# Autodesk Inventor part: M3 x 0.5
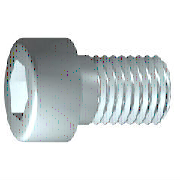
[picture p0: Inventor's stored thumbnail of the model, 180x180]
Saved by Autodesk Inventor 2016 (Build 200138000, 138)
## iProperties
IsCustomPart: 0
Created: 2015-10
Part Number: M3 x 0.5
Material: 강, 연강
Description: 6각머리 태핑 나사
Document SubType Name: Modeling
Standard: KS B 1003
Designer: mdu
Standards Organization: KS
Language: ko-KR
Size Designation: M 3 x 12
Categories: <MemberInstance><Categories><Category DisplayName="조임쇠" InternalName="e4da775c-781d-43d5-af7c-5136215cf5a6" Mnemonic="FSTN"><Category DisplayName="볼트" InternalN
Density: 1 g/cm^3
Appearance: 강철
Author: mdu
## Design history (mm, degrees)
sketch "스케치1"
  geometry: L1 (-0.867, 0)-(12, 0); L2 (12, 0)-(12, 1.5); L3 (12, 1.5)-(1.25, 1.5); L4 (1.25, 1.5)-(0.943, 1.5); L5 (0.943, 1.5)-(0, 1.5); L6 (0, 1.5)-(0, 2.75); L7 (0, 2.75)-(-3, 2.75); L8 (-3, 2.75)-(-3, 1.443); L9 (-3, 1.443)-(-1.7, 1.443); L10 (-1.7, 1.443)-(-0.867, 0); L11 (-6, 0)-(15, 0) reference; L12 (0, -0.55)-(0, 3.3) reference; L13 (1.25, 1.5)-(0, 1.5)
  constraints: 22 end point, 6 parallel, 2 collinear, 2 perpendicular, 1 horizontal, 1 point on line
  dimensions: "d1" = 10.75 distance from line of L3.end L2 (= GEL); "d2" = 0.30683 distance of L4.end L3.end (computed from GAL); "d3" = 3 distance between parallel lines of L8 L6 (= KOH); "d4" = 1.3 distance of L8.end L9.end (= INTI); "d5" = 60 deg angle of L10 L1; "d6" = 3 diameter of L3 L1 (= GD); "d7" = 3 diameter of L5 L1 (= BDM); "d8" = 2.88675 diameter of L9 L1 (= 1.1547 x SW); "d9" = 5.5 diameter of L7 L1 (= KOD); "d26" = 12 distance between parallel lines of L12 L2 (= NLG)
revolve "본체" sketch "스케치1" stored, may be unused: angle "d10" = 90 deg
sketch "스케치2"
  geometry: L1 (0, -3.85)-(0, 3.85) reference; L2 (-3.85, 0)-(3.85, 0) reference; L3 (1.443, 0)-(0.722, -1.25); L4 (0.722, -1.25)-(-0.722, -1.25); L5 (-0.722, -1.25)-(-1.443, 0); L6 (-1.443, 0)-(-0.722, 1.25); L7 (-0.722, 1.25)-(0.722, 1.25); L8 (0.722, 1.25)-(1.443, 0); 2 further points
  constraints: 12 end point, 1 coincident, 1 horizontal alignment, 1 point on line, 12 other
extrude "슬롯" join sketch "스케치2" stored distance "d11" = 10; taper "d12" = 0 deg
workplane "Work Plane1"
fillet "Fillet2" dims "d30" = 0.1 (= R)
body "Solid1"
fillet "모깎기1" dims "d17" = 0.3 (= RR)
feature "스레드" dims "d13" = 10.75 (= GEL), "d14" = 0
chamfer "모따기1" distance "d15" = 0.30673 (= -0.5 x SPD + 0.5 x GD); stored, may be unused: second distance "d16" = 0.30673 (= GUL), angle "d27" = 45 deg
other parameters: "GD" = 3 (= NND) [user parameter; used in 2 equation terms], "NLG" = 12 [user parameter; used in 1 equation term], "GEL" = 10.75 [user parameter; used in 2 equation terms], "KOD" = 5.5 [user parameter; used in 1 equation term], "KOH" = 3 [user parameter; used in 1 equation term], "INTI" = 1.3 [user parameter; used in 1 equation term], "GAL" = 0.30673 (= 0.61345 x PTC) [user parameter; used in 1 equation term], "GUL" = 0.30673 (= 0.61345 x PTC) [user parameter; used in 1 equation term], "BDM" = 3 (= NND) [user parameter; used in 1 equation term], "SW" = 2.5 [user parameter; used in 2 equation terms], "RR" = 0.3 [user parameter; used in 1 equation term], "SPD" = 2.38655 (= NND - 1.2269 x PTC) [user parameter; used in 1 equation term], "d19" = 0, "d28" = 0, "d29" = 0, "R" = 0.1 [user parameter; used in 1 equation term], "PHH" = 0.1 [user parameter], "GD1" = 2.38655 (= THREADDIA - 1.2269 x PTC) [user parameter], "THREADDIA" = 3 [user parameter; used in 1 equation term], "FAWI" = 45 deg [user parameter], "PTC" = 0.5 [user parameter; used in 5 equation terms], "NND" = 3 [user parameter; used in 3 equation terms], "TOA" = 30 deg [user parameter], "E0" = 2.8875 (= 1.155 x SW) [user parameter]
